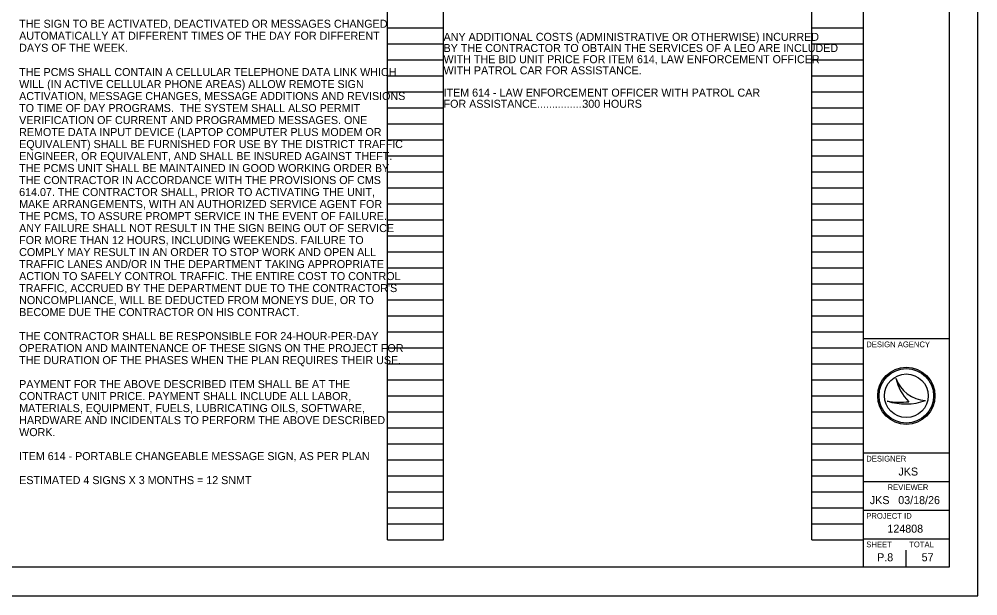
# Model space of a CAD drawing. Extents: x 0 to 34, y 0 to 22.
# Drawn here: x 17.24 to 34, y 0 to 10.09 of the extents above; entities that cross this region are included whole.
import ezdxf

# ---------------------------------------------------------------- set-up
doc = ezdxf.new("R2010")
doc.units = 0
for name, color, linetype in [('SH_Border', 7, 'Continuous'), ('SH_Cut_Line', 7, 'Continuous'), ('SH_Data', 7, 'Continuous'), ('SH_Text', 7, 'Continuous')]:
    doc.layers.add(name, color=color, linetype=linetype)

msp = doc.modelspace()

# ---------------------------------------------------------------- linework, layer by layer
at = {"layer": 'SH_Border'}
for p, q in [((32, 0.5), (32, 21.5)), ((32, 4.5), (33.5, 4.5)), ((32, 2.5), (33.5, 2.5)), ((32, 2), (33.5, 2)), ((32, 1.5), (33.5, 1.5)), ((32, 1), (33.5, 1))]:
    msp.add_line(p, q, dxfattribs=at)
msp.add_lwpolyline([(1.5, 21.5), (33.5, 21.5), (33.5, 0.5), (1.5, 0.5)], close=True, dxfattribs=at)
at = {"layer": 'SH_Cut_Line'}
msp.add_lwpolyline([(0, 0), (34, 0), (34, 22), (0, 22)], close=True, dxfattribs=at)
at = {"layer": 'SH_Data'}
for p, q in [((23.68, 0.98), (23.68, 21.14)), ((24.66, 0.98), (24.66, 21.14)), ((31.1, 0.98), (31.1, 21.14)), ((32, 0.98), (32, 21.14)), ((23.68, 9.94), (24.66, 9.94)), ((31.1, 9.94), (32, 9.94)), ((23.68, 9.66), (24.66, 9.66)), ((31.1, 9.66), (32, 9.66)), ((23.68, 9.38), (24.66, 9.38)), ((31.1, 9.38), (32, 9.38)), ((23.68, 9.1), (24.66, 9.1)), ((31.1, 9.1), (32, 9.1)), ((23.68, 8.82), (24.66, 8.82)), ((31.1, 8.82), (32, 8.82)), ((23.68, 8.54), (24.66, 8.54)), ((31.1, 8.54), (32, 8.54)), ((23.68, 8.26), (24.66, 8.26)), ((31.1, 8.26), (32, 8.26)), ((23.68, 7.98), (24.66, 7.98)), ((31.1, 7.98), (32, 7.98)), ((23.68, 7.7), (24.66, 7.7)), ((31.1, 7.7), (32, 7.7)), ((23.68, 7.42), (24.66, 7.42)), ((31.1, 7.42), (32, 7.42)), ((23.68, 7.14), (24.66, 7.14)), ((31.1, 7.14), (32, 7.14)), ((23.68, 6.86), (24.66, 6.86)), ((31.1, 6.86), (32, 6.86)), ((23.68, 6.58), (24.66, 6.58)), ((31.1, 6.58), (32, 6.58)), ((23.68, 6.3), (24.66, 6.3)), ((31.1, 6.3), (32, 6.3)), ((23.68, 6.02), (24.66, 6.02)), ((31.1, 6.02), (32, 6.02)), ((23.68, 5.74), (24.66, 5.74)), ((31.1, 5.74), (32, 5.74)), ((23.68, 5.46), (24.66, 5.46)), ((31.1, 5.46), (32, 5.46)), ((23.68, 5.18), (24.66, 5.18)), ((31.1, 5.18), (32, 5.18)), ((23.68, 4.9), (24.66, 4.9)), ((31.1, 4.9), (32, 4.9)), ((23.68, 4.62), (24.66, 4.62)), ((31.1, 4.62), (32, 4.62)), ((23.68, 4.34), (24.66, 4.34)), ((31.1, 4.34), (32, 4.34)), ((23.68, 4.06), (24.66, 4.06)), ((31.1, 4.06), (32, 4.06)), ((23.68, 3.78), (24.66, 3.78)), ((31.1, 3.78), (32, 3.78)), ((32.567, 3.81), (32.567, 3.81)), ((23.68, 3.5), (24.66, 3.5)), ((31.1, 3.5), (32, 3.5)), ((32.417, 3.41), (32.417, 3.41)), ((32.75, 3.5), (32.75, 3.5)), ((33.087, 3.419), (33.087, 3.419)), ((23.68, 3.22), (24.66, 3.22)), ((31.1, 3.22), (32, 3.22)), ((23.68, 2.94), (24.66, 2.94)), ((31.1, 2.94), (32, 2.94)), ((23.68, 2.66), (24.66, 2.66)), ((31.1, 2.66), (32, 2.66)), ((23.68, 2.38), (24.66, 2.38)), ((31.1, 2.38), (32, 2.38)), ((23.68, 2.1), (24.66, 2.1)), ((31.1, 2.1), (32, 2.1)), ((23.68, 1.82), (24.66, 1.82)), ((31.1, 1.82), (32, 1.82)), ((23.68, 1.54), (24.66, 1.54)), ((31.1, 1.54), (32, 1.54)), ((23.68, 1.26), (24.66, 1.26)), ((31.1, 1.26), (32, 1.26)), ((23.68, 0.98), (24.66, 0.98)), ((31.1, 0.98), (32, 0.98)), ((32.375, 0.675), (32.375, 0.675)), ((32.75, 0.5), (32.75, 0.8))]:
    msp.add_line(p, q, dxfattribs=at)
for radius in [0.5, 0.477, 0.477, 0.382]:
    msp.add_circle((32.75, 3.5), radius, dxfattribs=at)
for centre, radius, start, end in [((33.116, 3.998), 0.58, 198.9257, 198.9319), ((33.347, 3.97), 0.796, 191.6379, 191.6421), ((33.116, 3.998), 0.58, 198.9319, 267.1657), ((33.347, 3.97), 0.796, 191.6421, 226.0947), ((32.739, 4.37), 1.013, 251.4576, 290.0832), ((32.648, 4.654), 1.266, 259.4964, 259.4995), ((32.739, 4.37), 1.013, 251.4527, 251.4576), ((32.648, 4.654), 1.266, 259.4995, 276.6672)]:
    msp.add_arc(centre, radius, start, end, dxfattribs=at)

# ---------------------------------------------------------------- texts
for s, height, p in [('DESIGN AGENCY', 0.1, (32.05, 4.35)), ('DESIGNER', 0.1, (32.05, 2.35)), ('JKS', 0.14, (32.612, 2.105)), ('REVIEWER', 0.1, (32.422, 1.85)), ('JKS', 0.14, (32.112, 1.605)), ('03/18/26', 0.14, (32.609, 1.605)), ('PROJECT ID', 0.1, (32.05, 1.35)), ('124808', 0.14, (32.419, 1.105)), ('SHEET', 0.1, (32.05, 0.85)), ('TOTAL', 0.1, (32.8, 0.85)), ('P.8', 0.14, (32.239, 0.605)), ('57', 0.14, (33.018, 0.605))]:
    msp.add_text(s, height=height, dxfattribs=at).set_placement(p)
at = {"layer": 'SH_Text'}
for s, p in [('THE SIGN TO BE ACTIVATED, DEACTIVATED OR MESSAGES CHANGED ', (17.24, 9.94)), ('AUTOMATICALLY AT DIFFERENT TIMES OF THE DAY FOR DIFFERENT ', (17.24, 9.73)), ('ANY ADDITIONAL COSTS (ADMINISTRATIVE OR OTHERWISE) INCURRED ', (24.66, 9.711)), ('DAYS OF THE WEEK.', (17.24, 9.52)), ('BY THE CONTRACTOR TO OBTAIN THE SERVICES OF A LEO ARE INCLUDED ', (24.66, 9.516)), ('WITH THE BID UNIT PRICE FOR ITEM 614, LAW ENFORCEMENT OFFICER ', (24.66, 9.32)), ('THE PCMS SHALL CONTAIN A CELLULAR TELEPHONE DATA LINK WHICH ', (17.24, 9.095)), ('WITH PATROL CAR FOR ASSISTANCE.', (24.66, 9.125)), ('WILL (IN ACTIVE CELLULAR PHONE AREAS) ALLOW REMOTE SIGN ', (17.24, 8.885)), ('ACTIVATION, MESSAGE CHANGES, MESSAGE ADDITIONS AND REVISIONS ', (17.24, 8.675)), ('ITEM 614 - LAW ENFORCEMENT OFFICER WITH PATROL CAR ', (24.66, 8.735)), ('TO TIME OF DAY PROGRAMS.  THE SYSTEM SHALL ALSO PERMIT ', (17.24, 8.465)), ('FOR ASSISTANCE.................', (24.66, 8.54)), ('300 HOURS', (27.086, 8.54)), ('VERIFICATION OF CURRENT AND PROGRAMMED MESSAGES. ONE ', (17.24, 8.255)), ('REMOTE DATA INPUT DEVICE (LAPTOP COMPUTER PLUS MODEM OR ', (17.24, 8.045)), ('EQUIVALENT) SHALL BE FURNISHED FOR USE BY THE DISTRICT TRAFFIC ', (17.24, 7.835)), ('ENGINEER, OR EQUIVALENT, AND SHALL BE INSURED AGAINST THEFT. ', (17.24, 7.625)), ('THE PCMS UNIT SHALL BE MAINTAINED IN GOOD WORKING ORDER BY ', (17.24, 7.415)), ('THE CONTRACTOR IN ACCORDANCE WITH THE PROVISIONS OF CMS ', (17.24, 7.205)), ('614.07. THE CONTRACTOR SHALL, PRIOR TO ACTIVATING THE UNIT, ', (17.24, 6.995)), ('MAKE ARRANGEMENTS, WITH AN AUTHORIZED SERVICE AGENT FOR ', (17.24, 6.785)), ('THE PCMS, TO ASSURE PROMPT SERVICE IN THE EVENT OF FAILURE. ', (17.24, 6.575)), ('ANY FAILURE SHALL NOT RESULT IN THE SIGN BEING OUT OF SERVICE ', (17.24, 6.365)), ('FOR MORE THAN 12 HOURS, INCLUDING WEEKENDS. FAILURE TO ', (17.24, 6.155)), ('COMPLY MAY RESULT IN AN ORDER TO STOP WORK AND OPEN ALL ', (17.24, 5.945)), ('TRAFFIC LANES AND/OR IN THE DEPARTMENT TAKING APPROPRIATE ', (17.24, 5.735)), ('ACTION TO SAFELY CONTROL TRAFFIC. THE ENTIRE COST TO CONTROL ', (17.24, 5.525)), ("TRAFFIC, ACCRUED BY THE DEPARTMENT DUE TO THE CONTRACTOR'S ", (17.24, 5.315)), ('NONCOMPLIANCE, WILL BE DEDUCTED FROM MONEYS DUE, OR TO ', (17.24, 5.105)), ('BECOME DUE THE CONTRACTOR ON HIS CONTRACT.', (17.24, 4.895)), ('THE CONTRACTOR SHALL BE RESPONSIBLE FOR 24-HOUR-PER-DAY ', (17.24, 4.475)), ('OPERATION AND MAINTENANCE OF THESE SIGNS ON THE PROJECT FOR ', (17.24, 4.265)), ('THE DURATION OF THE PHASES WHEN THE PLAN REQUIRES THEIR USE.', (17.24, 4.055)), ('PAYMENT FOR THE ABOVE DESCRIBED ITEM SHALL BE AT THE ', (17.24, 3.635)), ('CONTRACT UNIT PRICE. PAYMENT SHALL INCLUDE ALL LABOR, ', (17.24, 3.425)), ('MATERIALS, EQUIPMENT, FUELS, LUBRICATING OILS, SOFTWARE, ', (17.24, 3.215)), ('HARDWARE AND INCIDENTALS TO PERFORM THE ABOVE DESCRIBED ', (17.24, 3.005)), ('WORK.', (17.24, 2.795)), ('ITEM 614 - PORTABLE CHANGEABLE MESSAGE SIGN, AS PER PLAN', (17.24, 2.375)), ('ESTIMATED 4 SIGNS X 3 MONTHS = 12 SNMT', (17.24, 1.955))]:
    msp.add_text(s, height=0.14, dxfattribs=at).set_placement(p)

doc.saveas('drawing.dxf')
